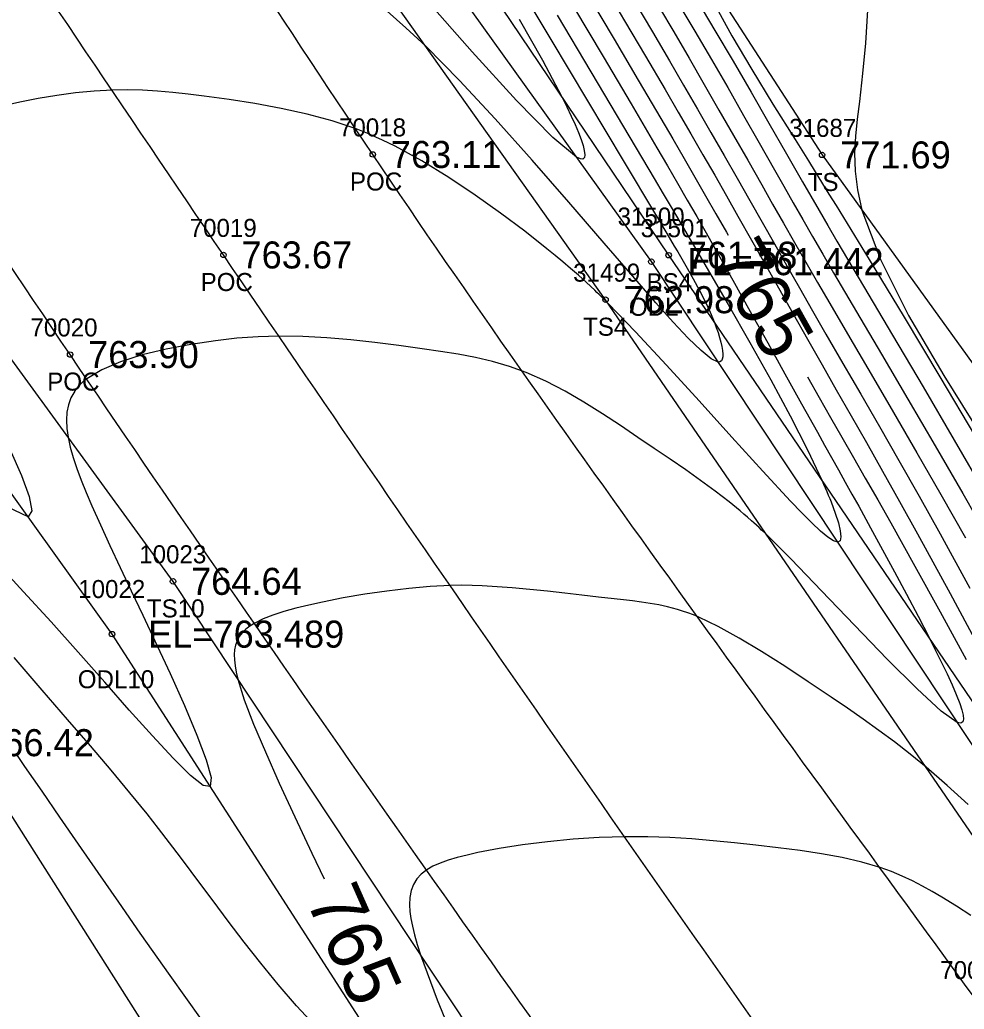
# Model space of a CAD drawing. Extents: x 1376587 to 1378239, y 1000335 to 1003031.
# Drawn here: x 1378018.9 to 1378071.2, y 1000532.4 to 1000587.3 of the extents above; entities that cross this region are included whole.
import ezdxf

# ---------------------------------------------------------------- set-up
doc = ezdxf.new("R2010")
doc.units = 0
for name, color, linetype in [('RD_DTM_BkLn1', 7, 'Continuous'), ('RD_DTM_BkLn2', 7, 'Continuous'), ('RD_DTM_BkLn_txCode', 7, 'Continuous'), ('RD_DTM_Major1', 7, 'Continuous'), ('RD_DTM_Major1_Lbl', 7, 'Continuous'), ('RD_DTM_Minor1', 7, 'Continuous'), ('RD_EX_H2O', 7, 'Continuous'), ('RD_EX_H2O_txCode', 7, 'Continuous'), ('RD_EX_Road', 7, 'Continuous'), ('RD_EX_Road_txCode', 7, 'Continuous'), ('RD_EX_TX_H2O_ELEV', 7, 'Continuous'), ('RD_EX_TX_Misc_ELEV', 7, 'Continuous'), ('RD_EX_TX_Road_ELEV', 7, 'Continuous'), ('RD_HC_Survey_ELEV', 7, 'Continuous'), ('RD_HC_Survey_txCode', 7, 'Continuous'), ('RD_SMD_Locator', 7, 'Continuous')]:
    doc.layers.add(name, color=color, linetype=linetype)

msp = doc.modelspace()

# ---------------------------------------------------------------- linework, layer by layer
at = {"layer": 'RD_DTM_BkLn1'}
msp.add_spline([(1378169.212, 1000387.103), (1378131.506, 1000434.744), (1378095.477, 1000481.988), (1378063.033, 1000526.867), (1378030.177, 1000574.233), (1377998.011, 1000622.539), (1377965.721, 1000673.201), (1377936, 1000721.493), (1377904.113, 1000773.429), (1377890.868, 1000795.129)], degree=3, dxfattribs=at)
at = {"layer": 'RD_DTM_BkLn2'}
for points in [[(1378190.398, 1000393.443), (1378169.827, 1000419.586), (1378140.073, 1000457.945), (1378106.638, 1000503.045), (1378080.309, 1000536.837), (1378054.858, 1000574.217), (1378031.288, 1000609.189), (1378023.609, 1000623.494), (1378023.602, 1000635.418), (1378048.247, 1000654.107), (1378063.88, 1000653.985)], [(1378152.795, 1000376.442), (1378153.623, 1000378.891), (1378133.341, 1000407.77), (1378106.208, 1000444.47), (1378079.422, 1000481.908), (1378052.603, 1000518.078), (1378027.38, 1000556.138), (1377999.887, 1000593.901), (1377975.443, 1000634.683), (1377966.188, 1000647.973)], [(1378152.458, 1000376.254), (1378150.255, 1000376.168), (1378128.245, 1000403.35), (1378101.014, 1000439.163), (1378072.773, 1000477.242), (1378039.24, 1000510.344), (1378015.855, 1000547.194), (1377989.301, 1000588.148), (1377962.727, 1000626.954), (1377952.76, 1000642.197)], [(1378184.932, 1000389.914), (1378162.528, 1000415.61), (1378132.296, 1000454.253), (1378102.474, 1000500.023), (1378076.88, 1000534.536), (1378051.356, 1000571.753), (1378025.282, 1000608.511), (1378019.607, 1000621.768)], [(1378038.697, 1000617.909), (1378063.36, 1000579.778), (1378090.166, 1000542.645), (1378113.6, 1000508.056), (1378141.542, 1000468.001), (1378167.145, 1000435.28), (1378192.427, 1000404.958)]]:
    msp.add_lwpolyline(points, dxfattribs=at)
at = {"layer": 'RD_DTM_Major1'}
for points in [[(1378050.416, 1000588.59), (1378051.829, 1000586.2), (1378053.172, 1000583.924), (1378054.421, 1000581.798), (1378055.081, 1000580.669), (1378055.709, 1000579.587), (1378056.313, 1000578.541), (1378056.901, 1000577.518), (1378057.479, 1000576.504), (1378058.055, 1000575.488), (1378058.147, 1000575.324)], [(1378056.418, 1000588.358), (1378057.424, 1000586.683), (1378058.427, 1000584.979), (1378059.424, 1000583.26), (1378060.41, 1000581.543), (1378061.382, 1000579.844), (1378061.829, 1000579.064), (1378062.277, 1000578.284), (1378062.732, 1000577.495), (1378063.198, 1000576.689), (1378063.681, 1000575.858), (1378064.185, 1000574.994), (1378065.653, 1000572.498), (1378067.261, 1000569.781), (1378068.957, 1000566.914), (1378070.69, 1000563.968), (1378072.411, 1000561.015)], [(1378062.55, 1000567.475), (1378063.202, 1000566.322), (1378063.824, 1000565.23), (1378064.453, 1000564.131), (1378065.095, 1000563.011), (1378065.756, 1000561.855), (1378066.444, 1000560.648), (1378067.165, 1000559.376), (1378068.504, 1000556.989), (1378069.913, 1000554.44), (1378071.344, 1000551.809)], [(1378071.455, 1000543.765), (1378070.29, 1000544.828), (1378069.13, 1000545.836), (1378068.247, 1000546.559), (1378067.377, 1000547.236), (1378066.512, 1000547.877), (1378065.644, 1000548.496), (1378064.767, 1000549.105), (1378063.871, 1000549.715), (1378062.593, 1000550.576), (1378061.296, 1000551.432), (1378060.011, 1000552.249), (1378058.769, 1000552.997), (1378057.601, 1000553.641), (1378056.538, 1000554.15), (1378056.225, 1000554.28), (1378055.923, 1000554.394), (1378055.63, 1000554.494), (1378055.345, 1000554.582), (1378055.065, 1000554.659), (1378054.788, 1000554.728), (1378054.313, 1000554.831), (1378053.836, 1000554.916), (1378053.353, 1000554.989), (1378052.86, 1000555.053), (1378052.353, 1000555.113), (1378051.828, 1000555.172), (1378050.959, 1000555.27), (1378050.045, 1000555.375), (1378049.1, 1000555.481), (1378048.132, 1000555.585), (1378047.155, 1000555.685), (1378046.178, 1000555.776), (1378045.631, 1000555.822), (1378045.081, 1000555.861), (1378044.525, 1000555.893), (1378043.958, 1000555.913), (1378043.373, 1000555.92), (1378042.766, 1000555.911), (1378041.638, 1000555.855), (1378040.452, 1000555.749), (1378039.235, 1000555.603), (1378038.014, 1000555.422), (1378036.817, 1000555.216), (1378035.671, 1000554.989), (1378034.907, 1000554.821), (1378034.189, 1000554.646), (1378033.524, 1000554.46), (1378032.92, 1000554.264), (1378032.384, 1000554.054), (1378031.923, 1000553.828), (1378031.646, 1000553.659), (1378031.409, 1000553.479), (1378031.212, 1000553.285), (1378031.052, 1000553.075), (1378030.929, 1000552.847), (1378030.841, 1000552.597), (1378030.792, 1000552.35), (1378030.771, 1000552.081), (1378030.779, 1000551.786), (1378030.816, 1000551.462), (1378030.882, 1000551.105), (1378030.976, 1000550.712), (1378031.332, 1000549.577), (1378031.846, 1000548.225), (1378032.498, 1000546.678), (1378033.267, 1000544.956), (1378034.135, 1000543.083), (1378035.08, 1000541.078), (1378035.76, 1000539.642)], [(1378035.27, 1000531.478), (1378034.22, 1000532.614), (1378033.21, 1000533.782), (1378032.241, 1000534.964), (1378031.316, 1000536.143), (1378030.434, 1000537.302), (1378029.598, 1000538.421), (1378028.982, 1000539.251), (1378028.383, 1000540.058), (1378027.79, 1000540.851), (1378027.192, 1000541.64), (1378026.579, 1000542.435), (1378025.94, 1000543.245), (1378024.988, 1000544.417), (1378023.949, 1000545.664), (1378022.804, 1000547.012), (1378021.537, 1000548.487), (1378020.131, 1000550.114), (1378018.569, 1000551.921)]]:
    msp.add_lwpolyline(points, dxfattribs=at)
at = {"layer": 'RD_DTM_Minor1'}
for points in [[(1378046.154, 1000589.794), (1378048.316, 1000586.183), (1378052.39, 1000579.382), (1378054.069, 1000576.575), (1378054.309, 1000576.175), (1378054.538, 1000575.79), (1378054.758, 1000575.421), (1378055.169, 1000574.727), (1378055.362, 1000574.4), (1378055.813, 1000573.626), (1378056.214, 1000572.918), (1378056.57, 1000572.264), (1378056.882, 1000571.651), (1378057.155, 1000571.066), (1378057.391, 1000570.496), (1378057.498, 1000570.21), (1378057.595, 1000569.928), (1378057.679, 1000569.655), (1378057.75, 1000569.395), (1378057.804, 1000569.152), (1378057.841, 1000568.93), (1378057.857, 1000568.741), (1378057.853, 1000568.579), (1378057.828, 1000568.448), (1378057.778, 1000568.354), (1378057.702, 1000568.3), (1378057.598, 1000568.29), (1378057.21, 1000568.473), (1378056.652, 1000568.928), (1378055.944, 1000569.619), (1378055.105, 1000570.514), (1378054.153, 1000571.576), (1378053.107, 1000572.771), (1378051.276, 1000574.89), (1378049.315, 1000577.164), (1378047.283, 1000579.493), (1378045.244, 1000581.775), (1378043.259, 1000583.913), (1378041.388, 1000585.805), (1378040.293, 1000586.833), (1378039.254, 1000587.746)], [(1378051.207, 1000589.26), (1378052.415, 1000587.211), (1378053.568, 1000585.255), (1378054.655, 1000583.402), (1378055.383, 1000582.155), (1378056.081, 1000580.954), (1378056.755, 1000579.788), (1378057.412, 1000578.647), (1378058.057, 1000577.518), (1378058.698, 1000576.391), (1378059.451, 1000575.059), (1378060.209, 1000573.713), (1378061.754, 1000570.967), (1378062.547, 1000569.564), (1378063.358, 1000568.136), (1378064.15, 1000566.75), (1378064.968, 1000565.321), (1378065.82, 1000563.828), (1378066.714, 1000562.252), (1378067.656, 1000560.574), (1378068.655, 1000558.773), (1378070.457, 1000555.47), (1378072.352, 1000551.951)], [(1378046.572, 1000587.301), (1378047.862, 1000585.024), (1378048.935, 1000583.006), (1378049.21, 1000582.452), (1378049.455, 1000581.936), (1378049.67, 1000581.46), (1378049.851, 1000581.028), (1378049.997, 1000580.642), (1378050.108, 1000580.305), (1378050.18, 1000580.017), (1378050.207, 1000579.79), (1378050.183, 1000579.632), (1378050.103, 1000579.55), (1378049.961, 1000579.553), (1378049.751, 1000579.646), (1378048.436, 1000580.743), (1378046.425, 1000582.799), (1378043.972, 1000585.49), (1378041.332, 1000588.494)], [(1378052.987, 1000588.251), (1378053.96, 1000586.594), (1378054.895, 1000584.998), (1378055.686, 1000583.64), (1378056.453, 1000582.317), (1378057.201, 1000581.022), (1378057.932, 1000579.75), (1378058.65, 1000578.494), (1378059.36, 1000577.247), (1378060.039, 1000576.05), (1378060.719, 1000574.848), (1378061.406, 1000573.634), (1378062.107, 1000572.401), (1378062.826, 1000571.139), (1378063.571, 1000569.841), (1378064.514, 1000568.211), (1378065.503, 1000566.507), (1378066.536, 1000564.721), (1378067.615, 1000562.843), (1378068.739, 1000560.864), (1378069.907, 1000558.774), (1378071.559, 1000555.76)], [(1378049.588, 1000587.987), (1378051.219, 1000585.234), (1378052.773, 1000582.605), (1378054.205, 1000580.167), (1378054.79, 1000579.166), (1378055.348, 1000578.205), (1378055.887, 1000577.273), (1378056.412, 1000576.359), (1378056.93, 1000575.451), (1378057.447, 1000574.54), (1378058.411, 1000572.828), (1378059.382, 1000571.091), (1378060.348, 1000569.354), (1378061.298, 1000567.643), (1378062.219, 1000565.983), (1378063.1, 1000564.401), (1378063.496, 1000563.691), (1378063.884, 1000562.999), (1378064.264, 1000562.318), (1378064.641, 1000561.645), (1378065.016, 1000560.973), (1378065.392, 1000560.297), (1378066.053, 1000559.102), (1378066.718, 1000557.888), (1378067.382, 1000556.661), (1378068.04, 1000555.431), (1378068.685, 1000554.204), (1378069.312, 1000552.988), (1378069.657, 1000552.308), (1378069.987, 1000551.644), (1378070.293, 1000551.008), (1378070.568, 1000550.409), (1378070.804, 1000549.858), (1378070.994, 1000549.367), (1378071.11, 1000549.013), (1378071.18, 1000548.717), (1378071.198, 1000548.489), (1378071.156, 1000548.341), (1378071.045, 1000548.281), (1378070.859, 1000548.322), (1378069.972, 1000548.945), (1378068.629, 1000550.176), (1378066.977, 1000551.825), (1378065.164, 1000553.7), (1378063.337, 1000555.61), (1378061.643, 1000557.364), (1378061.404, 1000557.607), (1378061.172, 1000557.842), (1378060.947, 1000558.068), (1378060.729, 1000558.285), (1378060.518, 1000558.493), (1378060.314, 1000558.691), (1378060.161, 1000558.838), (1378060.011, 1000558.98), (1378059.866, 1000559.117), (1378059.724, 1000559.249), (1378059.584, 1000559.376), (1378059.448, 1000559.5), (1378059.236, 1000559.688), (1378059.028, 1000559.868), (1378058.824, 1000560.043), (1378058.622, 1000560.211), (1378058.421, 1000560.376), (1378058.22, 1000560.538), (1378057.434, 1000561.146), (1378056.629, 1000561.736), (1378055.8, 1000562.319), (1378054.944, 1000562.904), (1378054.058, 1000563.502), (1378053.139, 1000564.12), (1378052.178, 1000564.769), (1378051.184, 1000565.428), (1378050.16, 1000566.074), (1378049.11, 1000566.686), (1378048.039, 1000567.243), (1378046.95, 1000567.721), (1378046.031, 1000568.049), (1378045.099, 1000568.318), (1378044.152, 1000568.54), (1378043.187, 1000568.726), (1378042.202, 1000568.888), (1378041.194, 1000569.037), (1378039.899, 1000569.216), (1378038.576, 1000569.382), (1378037.239, 1000569.526), (1378035.9, 1000569.638), (1378034.574, 1000569.709), (1378033.272, 1000569.729), (1378032.68, 1000569.718), (1378032.093, 1000569.695), (1378031.508, 1000569.659), (1378030.922, 1000569.611), (1378030.332, 1000569.55), (1378029.733, 1000569.478), (1378028.363, 1000569.275), (1378026.993, 1000569.013), (1378025.678, 1000568.692), (1378024.47, 1000568.311), (1378023.425, 1000567.872), (1378022.596, 1000567.372), (1378022.46, 1000567.264), (1378022.334, 1000567.154), (1378022.219, 1000567.04), (1378022.113, 1000566.924), (1378022.016, 1000566.805), (1378021.929, 1000566.684), (1378021.723, 1000566.317), (1378021.583, 1000565.926), (1378021.501, 1000565.511), (1378021.474, 1000565.073), (1378021.496, 1000564.612), (1378021.562, 1000564.129), (1378021.68, 1000563.578), (1378021.842, 1000562.999), (1378022.045, 1000562.388), (1378022.288, 1000561.742), (1378022.567, 1000561.058), (1378022.879, 1000560.332), (1378023.355, 1000559.265), (1378023.883, 1000558.119), (1378024.455, 1000556.899), (1378025.065, 1000555.61), (1378025.705, 1000554.257), (1378026.37, 1000552.846), (1378027.213, 1000551.032), (1378028.014, 1000549.251), (1378028.706, 1000547.618), (1378029.22, 1000546.249), (1378029.488, 1000545.257), (1378029.442, 1000544.759), (1378029.046, 1000544.826), (1378028.341, 1000545.381), (1378027.385, 1000546.327), (1378026.238, 1000547.567), (1378024.957, 1000549.005), (1378023.601, 1000550.544), (1378022.121, 1000552.213), (1378020.619, 1000553.887), (1378019.093, 1000555.564), (1378017.54, 1000557.245)], [(1378054.352, 1000587.938), (1378055.136, 1000586.597), (1378055.988, 1000585.134), (1378056.824, 1000583.69), (1378057.645, 1000582.267), (1378058.45, 1000580.863), (1378059.242, 1000579.479), (1378060.02, 1000578.115), (1378060.622, 1000577.056), (1378061.225, 1000575.997), (1378061.834, 1000574.928), (1378062.459, 1000573.836), (1378063.107, 1000572.71), (1378063.785, 1000571.539), (1378064.892, 1000569.644), (1378066.075, 1000567.626), (1378067.321, 1000565.496), (1378068.618, 1000563.265), (1378069.951, 1000560.944), (1378071.307, 1000558.542)], [(1378055.372, 1000588.216), (1378056.31, 1000586.637), (1378057.229, 1000585.065), (1378058.129, 1000583.507), (1378059.011, 1000581.965), (1378059.875, 1000580.446), (1378060.722, 1000578.955), (1378061.241, 1000578.039), (1378061.762, 1000577.124), (1378062.29, 1000576.199), (1378062.834, 1000575.252), (1378063.4, 1000574.271), (1378063.997, 1000573.244), (1378065.268, 1000571.077), (1378066.651, 1000568.73), (1378068.115, 1000566.243), (1378069.63, 1000563.657), (1378071.162, 1000561.009), (1378072.683, 1000558.34)], [(1378057.391, 1000588.127), (1378058.365, 1000586.374), (1378059.461, 1000584.521), (1378060.64, 1000582.598), (1378061.863, 1000580.633), (1378062.233, 1000580.04), (1378062.605, 1000579.443), (1378062.98, 1000578.84), (1378063.745, 1000577.609), (1378064.136, 1000576.975), (1378065.975, 1000573.978), (1378067.916, 1000570.778), (1378069.898, 1000567.472), (1378071.862, 1000564.156)], [(1378065.876, 1000587.811), (1378065.762, 1000585.98), (1378065.611, 1000584.295), (1378065.435, 1000582.736), (1378065.316, 1000581.767), (1378065.218, 1000580.82), (1378065.167, 1000579.867), (1378065.192, 1000578.883), (1378065.318, 1000577.841), (1378065.571, 1000576.715), (1378066.592, 1000573.976), (1378068.146, 1000570.882), (1378070.11, 1000567.555), (1378072.174, 1000564.226)], [(1378048.668, 1000587.525), (1378050.537, 1000584.383), (1378052.35, 1000581.335), (1378054.048, 1000578.477), (1378054.553, 1000577.626), (1378055.044, 1000576.796), (1378055.525, 1000575.982), (1378055.999, 1000575.176), (1378056.471, 1000574.373), (1378056.944, 1000573.565), (1378058.153, 1000571.482), (1378059.355, 1000569.378), (1378060.513, 1000567.303), (1378061.59, 1000565.305), (1378062.549, 1000563.435), (1378063.352, 1000561.742), (1378063.446, 1000561.531), (1378063.537, 1000561.323), (1378063.623, 1000561.121), (1378063.707, 1000560.922), (1378063.786, 1000560.729), (1378063.861, 1000560.54), (1378064.091, 1000559.927), (1378064.264, 1000559.389), (1378064.372, 1000558.942), (1378064.408, 1000558.602), (1378064.363, 1000558.385), (1378064.228, 1000558.306), (1378064, 1000558.377), (1378063.681, 1000558.588), (1378063.277, 1000558.927), (1378062.795, 1000559.382), (1378062.241, 1000559.939), (1378061.62, 1000560.588), (1378060.083, 1000562.243), (1378058.359, 1000564.136), (1378056.544, 1000566.141), (1378054.731, 1000568.13), (1378053.017, 1000569.975), (1378051.497, 1000571.547), (1378051.242, 1000571.801), (1378051.118, 1000571.923), (1378050.996, 1000572.042), (1378050.875, 1000572.159), (1378050.757, 1000572.272), (1378050.298, 1000572.703), (1378049.856, 1000573.104), (1378049.424, 1000573.484), (1378048.994, 1000573.849), (1378048.559, 1000574.209), (1378048.112, 1000574.571), (1378046.876, 1000575.543), (1378045.538, 1000576.549), (1378044.125, 1000577.556), (1378042.662, 1000578.532), (1378041.176, 1000579.443), (1378039.694, 1000580.257), (1378039.339, 1000580.434), (1378038.985, 1000580.605), (1378038.63, 1000580.768), (1378038.271, 1000580.925), (1378037.907, 1000581.075), (1378037.536, 1000581.218), (1378036.208, 1000581.662), (1378034.81, 1000582.04), (1378033.373, 1000582.359), (1378031.923, 1000582.627), (1378030.489, 1000582.851), (1378029.099, 1000583.04), (1378028.219, 1000583.148), (1378027.362, 1000583.239), (1378026.522, 1000583.312), (1378025.691, 1000583.36), (1378024.86, 1000583.382), (1378024.023, 1000583.372), (1378023.003, 1000583.316), (1378021.971, 1000583.215), (1378020.936, 1000583.076), (1378019.908, 1000582.903), (1378018.895, 1000582.704), (1378017.906, 1000582.483)], [(1378018.332, 1000563.463), (1378018.972, 1000562.007), (1378019.399, 1000560.837), (1378019.546, 1000560.042), (1378019.341, 1000559.714), (1378018.219, 1000560.254)], [(1378028.959, 1000531.855), (1378027.214, 1000534.287), (1378025.567, 1000536.634), (1378024.368, 1000538.356), (1378023.229, 1000540), (1378022.144, 1000541.569), (1378021.11, 1000543.067), (1378020.121, 1000544.501), (1378019.173, 1000545.873), (1378018.713, 1000546.536)], [(1378071.615, 1000537.621), (1378070.805, 1000538.133), (1378069.999, 1000538.624), (1378069.466, 1000538.939), (1378068.927, 1000539.242), (1378068.376, 1000539.53), (1378067.806, 1000539.802), (1378067.208, 1000540.053), (1378066.576, 1000540.282), (1378065.567, 1000540.578), (1378064.481, 1000540.826), (1378063.336, 1000541.035), (1378062.145, 1000541.213), (1378060.923, 1000541.37), (1378059.687, 1000541.512), (1378058.51, 1000541.641), (1378057.327, 1000541.758), (1378056.135, 1000541.857), (1378054.928, 1000541.931), (1378053.702, 1000541.975), (1378052.451, 1000541.98), (1378051.009, 1000541.934), (1378049.56, 1000541.839), (1378048.132, 1000541.7), (1378046.755, 1000541.526), (1378045.459, 1000541.323), (1378044.273, 1000541.097), (1378043.683, 1000540.967), (1378043.136, 1000540.829), (1378042.636, 1000540.68), (1378042.186, 1000540.519), (1378041.787, 1000540.341), (1378041.443, 1000540.144), (1378041.135, 1000539.906), (1378040.89, 1000539.638), (1378040.706, 1000539.337), (1378040.58, 1000538.999), (1378040.51, 1000538.62), (1378040.493, 1000538.196), (1378040.515, 1000537.84), (1378040.566, 1000537.45), (1378040.65, 1000537.02), (1378040.767, 1000536.543), (1378040.918, 1000536.014), (1378041.106, 1000535.427), (1378042.02, 1000532.947), (1378043.259, 1000529.93)]]:
    msp.add_lwpolyline(points, dxfattribs=at)
at = {"layer": 'RD_EX_H2O'}
for points in [[(1378150.92, 1000378.554), (1378129.931, 1000405.361), (1378103.429, 1000442.377), (1378075.971, 1000479.612), (1378048.045, 1000515.879), (1378023.997, 1000553.212), (1377996.392, 1000591.758), (1377970.527, 1000631.657), (1377963.482, 1000646.08)], [(1378187.963, 1000391.619), (1378166.952, 1000418.069), (1378136.831, 1000457.58), (1378104.578, 1000501.856), (1378079.015, 1000536.042), (1378053.898, 1000573.861), (1378029.308, 1000608.167), (1378022.926, 1000618.73)]]:
    msp.add_lwpolyline(points, dxfattribs=at)
at = {"layer": 'RD_EX_Road'}
for points in [[(1378177.15, 1000392.854), (1378139.733, 1000441.521), (1378104.671, 1000487.69), (1378071.786, 1000533.085), (1378038.454, 1000579.804), (1378007.554, 1000627.96), (1377974.27, 1000678.859), (1377944.465, 1000727.117), (1377913.028, 1000778.581), (1377899.668, 1000800.294)], [(1378161.362, 1000381.162), (1378123.914, 1000428.538), (1378087.578, 1000476.324), (1378055.075, 1000520.944), (1378021.673, 1000568.713), (1377989.952, 1000617.081), (1377957.327, 1000668.378), (1377927.534, 1000716.552), (1377895.409, 1000768.824), (1377883.752, 1000788.501)]]:
    msp.add_spline(points, degree=3, dxfattribs=at)
at = {"layer": 'RD_SMD_Locator'}
for centre in [(1378038.454, 1000579.804), (1378063.36, 1000579.778), (1378030.177, 1000574.233), (1378053.898, 1000573.861), (1378054.858, 1000574.217), (1378051.356, 1000571.753), (1378021.673, 1000568.713), (1378027.38, 1000556.138), (1378023.997, 1000553.212)]:
    msp.add_circle(centre, 0.15, dxfattribs=at)

# ---------------------------------------------------------------- texts
at = {"layer": 'RD_DTM_BkLn_txCode'}
for s, p in [('31687', (1378061.541, 1000580.778)), ('TS', (1378062.565, 1000577.778)), ('31501', (1378053.307, 1000575.217)), ('31499', (1378049.561, 1000572.753)), ('BS4', (1378053.63, 1000572.217)), ('TS4', (1378050.112, 1000569.753)), ('10023', (1378025.506, 1000557.138)), ('TS10', (1378025.931, 1000554.138))]:
    msp.add_text(s, height=1, dxfattribs=at).set_placement(p)
at = {"layer": 'RD_DTM_Major1_Lbl'}
for rotation, p in [(299.2897, (1378057.145, 1000574.044)), (293.9203, (1378034.721, 1000538.498))]:
    msp.add_text('765', height=3, rotation=rotation, dxfattribs=at).set_placement(p)
at = {"layer": 'RD_EX_H2O_txCode'}
for s, p in [('31500', (1378052.024, 1000575.861)), ('ODL', (1378052.654, 1000570.861)), ('10022', (1378022.123, 1000555.212)), ('ODL10', (1378022.099, 1000550.212))]:
    msp.add_text(s, height=1, dxfattribs=at).set_placement(p)
at = {"layer": 'RD_EX_Road_txCode'}
for s, p in [('70018', (1378036.58, 1000580.804)), ('POC', (1378037.186, 1000577.804)), ('70020', (1378019.476, 1000569.713)), ('POC', (1378020.405, 1000566.713)), ('70017', (1378069.912, 1000534.085))]:
    msp.add_text(s, height=1, dxfattribs=at).set_placement(p)
at = {"layer": 'RD_EX_TX_H2O_ELEV'}
for s, p in [('EL=761.442', (1378055.898, 1000573.111)), ('EL=763.489', (1378025.997, 1000552.462))]:
    msp.add_text(s, height=1.5, dxfattribs=at).set_placement(p)
at = {"layer": 'RD_EX_TX_Misc_ELEV'}
for s, p in [('771.69', (1378064.36, 1000579.028)), ('761.58', (1378055.858, 1000573.467)), ('762.98', (1378052.356, 1000571.003)), ('764.64', (1378028.38, 1000555.388)), ('766.42', (1378016.855, 1000546.444))]:
    msp.add_text(s, height=1.5, dxfattribs=at).set_placement(p)
at = {"layer": 'RD_EX_TX_Road_ELEV'}
for s, p in [('763.11', (1378039.454, 1000579.054)), ('763.90', (1378022.673, 1000567.963))]:
    msp.add_text(s, height=1.5, dxfattribs=at).set_placement(p)
at = {"layer": 'RD_HC_Survey_ELEV'}
msp.add_text('763.67', height=1.5, dxfattribs=at).set_placement((1378031.177, 1000573.483))
at = {"layer": 'RD_HC_Survey_txCode'}
for s, p in [('70019', (1378028.303, 1000575.233)), ('POC', (1378028.909, 1000572.233))]:
    msp.add_text(s, height=1, dxfattribs=at).set_placement(p)

doc.saveas('drawing.dxf')
